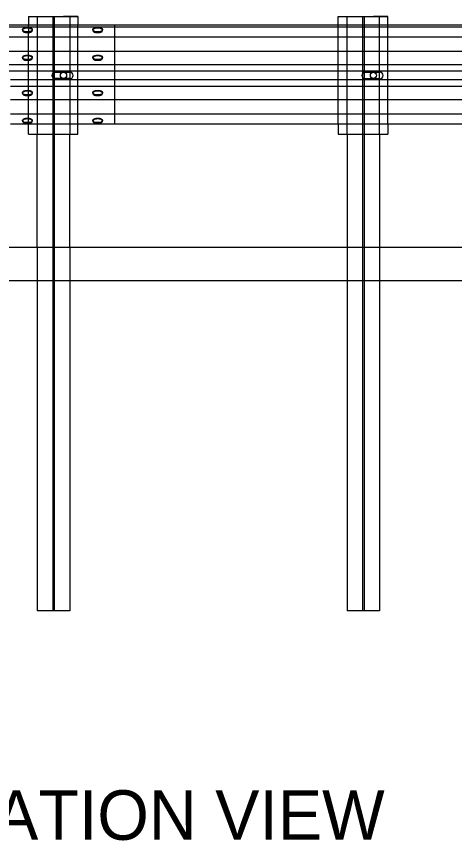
# Model space of a CAD drawing. Extents: x 49991 to 50160, y 49948 to 50051.
# Drawn here: x 50063.48 to 50067.89, y 50002.88 to 50011.2 of the extents above; entities that cross this region are included whole.
import ezdxf

# ---------------------------------------------------------------- set-up
doc = ezdxf.new("R2010")
doc.units = 0
for name, color, linetype in [('Level 1', 7, 'Continuous'), ('Level 3', 7, 'Continuous'), ('Level 4', 7, 'Continuous')]:
    doc.layers.add(name, color=color, linetype=linetype)

msp = doc.modelspace()

# ---------------------------------------------------------------- linework, layer by layer
at = {"layer": 'Level 1'}
for p, q in [((50063.598, 50011.2015), (50064.098, 50011.2015)), ((50063.598, 50011.2015), (50063.598, 50011.1187)), ((50063.6863, 50011.2015), (50064.0146, 50011.2015)), ((50064.098, 50011.2015), (50063.9521, 50011.2015)), ((50064.098, 50011.2015), (50064.098, 50011.1187)), ((50066.723, 50011.2014), (50067.223, 50011.2014)), ((50066.723, 50011.1185), (50066.723, 50011.2014)), ((50066.8113, 50011.2014), (50067.1396, 50011.2014)), ((50067.223, 50011.2014), (50067.0771, 50011.2014)), ((50067.223, 50011.1185), (50067.223, 50011.2014)), ((50057.4018, 50011.1191), (50093.8271, 50011.1169)), ((50057.4018, 50011.0986), (50093.8271, 50011.0968)), ((50063.5389, 50011.0689), (50063.5389, 50011.0616)), ((50063.5783, 50011.0909), (50063.598, 50011.0909)), ((50063.5783, 50011.0837), (50063.5783, 50011.0909)), ((50063.598, 50011.0837), (50063.5783, 50011.0837)), ((50063.598, 50011.0837), (50063.598, 50011.0909)), ((50063.598, 50011.0837), (50063.598, 50011.0469)), ((50063.6374, 50011.0616), (50063.6374, 50011.0689)), ((50064.287, 50011.0837), (50064.287, 50011.0909)), ((50064.287, 50011.0909), (50064.3066, 50011.0909)), ((50064.3066, 50011.0837), (50064.287, 50011.0837)), ((50064.3066, 50011.0837), (50064.3066, 50011.0909)), ((50064.346, 50011.0616), (50064.346, 50011.0689)), ((50058.2173, 50010.9976), (50093.8271, 50010.9976)), ((50063.598, 50011.0469), (50063.5783, 50011.0469)), ((50063.5783, 50011.0396), (50063.5783, 50011.0469)), ((50063.5783, 50011.0396), (50063.598, 50011.0396)), ((50063.598, 50011.0396), (50063.598, 50011.0469)), ((50064.3066, 50011.0469), (50064.287, 50011.0469)), ((50064.287, 50011.0396), (50064.287, 50011.0469)), ((50064.287, 50011.0396), (50064.3066, 50011.0396)), ((50064.3066, 50011.0396), (50064.3066, 50011.0469)), ((50058.2173, 50010.8525), (50093.8271, 50010.8493)), ((50063.5389, 50010.7885), (50063.5389, 50010.7812)), ((50063.5783, 50010.8105), (50063.598, 50010.8105)), ((50063.5783, 50010.8105), (50063.5783, 50010.8033)), ((50063.598, 50010.8033), (50063.5783, 50010.8033)), ((50063.5783, 50010.7665), (50063.5783, 50010.7592)), ((50063.598, 50010.7665), (50063.5783, 50010.7665)), ((50063.5783, 50010.7592), (50063.598, 50010.7592)), ((50063.598, 50010.8105), (50063.598, 50010.8033)), ((50063.598, 50010.7665), (50063.598, 50010.8033)), ((50063.598, 50010.7665), (50063.598, 50010.7592)), ((50063.6374, 50010.7812), (50063.6374, 50010.7885)), ((50064.287, 50010.8105), (50064.3066, 50010.8105)), ((50064.287, 50010.8105), (50064.287, 50010.8033)), ((50064.3066, 50010.8033), (50064.287, 50010.8033)), ((50064.287, 50010.7665), (50064.287, 50010.7592)), ((50064.3066, 50010.7665), (50064.287, 50010.7665)), ((50064.287, 50010.7592), (50064.3066, 50010.7592)), ((50064.3066, 50010.8105), (50064.3066, 50010.8033)), ((50064.3066, 50010.7665), (50064.3066, 50010.7592)), ((50064.346, 50010.7812), (50064.346, 50010.7885)), ((50058.2173, 50010.717), (50093.8271, 50010.722)), ((50060.8961, 50010.6545), (50093.8271, 50010.6434)), ((50063.8687, 50010.6396), (50064.0163, 50010.6396)), ((50064.0163, 50010.574), (50063.8687, 50010.574)), ((50066.9935, 50010.6392), (50067.1412, 50010.6392)), ((50067.1412, 50010.5736), (50066.9935, 50010.5736)), ((50093.8271, 50010.5604), (50063.4175, 50010.5609)), ((50093.8271, 50010.4957), (50063.4175, 50010.4957)), ((50063.5389, 50010.4324), (50063.5389, 50010.4252)), ((50063.5783, 50010.4545), (50063.598, 50010.4545)), ((50063.5783, 50010.4472), (50063.5783, 50010.4545)), ((50063.598, 50010.4472), (50063.5783, 50010.4472)), ((50063.598, 50010.4104), (50063.5783, 50010.4104)), ((50063.5783, 50010.4031), (50063.5783, 50010.4104)), ((50063.5783, 50010.4031), (50063.598, 50010.4031)), ((50063.598, 50010.4472), (50063.598, 50010.4545)), ((50063.598, 50010.4104), (50063.598, 50010.4472)), ((50063.598, 50010.4031), (50063.598, 50010.4104)), ((50063.6374, 50010.4252), (50063.6374, 50010.4324)), ((50064.287, 50010.4545), (50064.3066, 50010.4545)), ((50064.287, 50010.4472), (50064.287, 50010.4545)), ((50064.3066, 50010.4472), (50064.287, 50010.4472)), ((50064.3066, 50010.4104), (50064.287, 50010.4104)), ((50064.287, 50010.4031), (50064.287, 50010.4104)), ((50064.287, 50010.4031), (50064.3066, 50010.4031)), ((50064.3066, 50010.4472), (50064.3066, 50010.4545)), ((50064.3066, 50010.4031), (50064.3066, 50010.4104)), ((50064.346, 50010.4252), (50064.346, 50010.4324)), ((50093.8271, 50010.3615), (50063.4175, 50010.3611)), ((50093.8271, 50010.2161), (50063.4175, 50010.2161)), ((50063.5783, 50010.1741), (50063.598, 50010.1741)), ((50063.5783, 50010.1741), (50063.5783, 50010.1668)), ((50063.598, 50010.1668), (50063.5783, 50010.1668)), ((50063.598, 50010.1741), (50063.598, 50010.1668)), ((50063.598, 50010.13), (50063.598, 50010.1668)), ((50064.287, 50010.1741), (50064.3066, 50010.1741)), ((50064.287, 50010.1741), (50064.287, 50010.1668)), ((50064.3066, 50010.1668), (50064.287, 50010.1668)), ((50064.3066, 50010.1741), (50064.3066, 50010.1668)), ((50093.8271, 50010.1154), (50063.4175, 50010.1154)), ((50063.5389, 50010.152), (50063.5389, 50010.1448)), ((50063.5783, 50010.13), (50063.5783, 50010.1227)), ((50063.598, 50010.13), (50063.5783, 50010.13)), ((50063.5783, 50010.1227), (50063.598, 50010.1227)), ((50063.598, 50010.13), (50063.598, 50010.1227)), ((50063.598, 50010.014), (50063.598, 50010.1154)), ((50063.6374, 50010.1448), (50063.6374, 50010.152)), ((50064.098, 50010.014), (50064.098, 50010.1154)), ((50064.287, 50010.13), (50064.287, 50010.1227)), ((50064.3066, 50010.13), (50064.287, 50010.13)), ((50064.287, 50010.1227), (50064.3066, 50010.1227)), ((50064.3066, 50010.13), (50064.3066, 50010.1227)), ((50064.346, 50010.1448), (50064.346, 50010.152)), ((50066.723, 50010.1154), (50066.723, 50010.0139)), ((50067.223, 50010.1154), (50067.223, 50010.0139)), ((50063.598, 50010.014), (50064.098, 50010.014)), ((50063.6863, 50008.8682), (50063.6863, 50010.014)), ((50064.0146, 50008.8682), (50064.0146, 50010.014)), ((50066.723, 50010.0139), (50067.223, 50010.0139)), ((50066.8113, 50010.0139), (50066.8113, 50008.868)), ((50067.1396, 50010.0139), (50067.1396, 50008.868)), ((50093.8271, 50008.8669), (50039.5562, 50008.8692)), ((50034.588, 50008.5361), (50093.8271, 50008.5336))]:
    msp.add_line(p, q, dxfattribs=at)
for points in [[(50063.5783, 50011.0469), (50063.5715, 50011.0472), (50063.5648, 50011.0482), (50063.5586, 50011.0498), (50063.553, 50011.052), (50063.5481, 50011.0547), (50063.5442, 50011.0579), (50063.5413, 50011.0614), (50063.5395, 50011.0651), (50063.5389, 50011.0689), (50063.5395, 50011.0727), (50063.5413, 50011.0764), (50063.5442, 50011.0799), (50063.5481, 50011.0831), (50063.553, 50011.0858), (50063.5586, 50011.088), (50063.5648, 50011.0896), (50063.5715, 50011.0906), (50063.5783, 50011.0909)], [(50063.5783, 50011.0837), (50063.5715, 50011.0833), (50063.5648, 50011.0824), (50063.5586, 50011.0807), (50063.553, 50011.0785), (50063.5481, 50011.0758), (50063.5442, 50011.0727), (50063.5413, 50011.0692), (50063.5395, 50011.0655), (50063.5395, 50011.0653)], [(50063.598, 50011.0909), (50063.6048, 50011.0906), (50063.6115, 50011.0896), (50063.6177, 50011.088), (50063.6233, 50011.0858), (50063.6281, 50011.0831), (50063.6321, 50011.0799), (50063.635, 50011.0764), (50063.6368, 50011.0727), (50063.6374, 50011.0689), (50063.6368, 50011.0651), (50063.635, 50011.0614), (50063.6321, 50011.0579), (50063.6281, 50011.0547), (50063.6233, 50011.052), (50063.6177, 50011.0498), (50063.6115, 50011.0482), (50063.6048, 50011.0472), (50063.598, 50011.0469)], [(50063.6368, 50011.0653), (50063.6368, 50011.0655), (50063.635, 50011.0692), (50063.6321, 50011.0727), (50063.6281, 50011.0758), (50063.6233, 50011.0785), (50063.6177, 50011.0807), (50063.6115, 50011.0824), (50063.6048, 50011.0833), (50063.598, 50011.0837)], [(50064.287, 50011.0469), (50064.2801, 50011.0472), (50064.2735, 50011.0482), (50064.2673, 50011.0498), (50064.2617, 50011.052), (50064.2568, 50011.0547), (50064.2529, 50011.0579), (50064.25, 50011.0614), (50064.2482, 50011.0651), (50064.2476, 50011.0689), (50064.2482, 50011.0727), (50064.25, 50011.0764), (50064.2529, 50011.0799), (50064.2568, 50011.0831), (50064.2617, 50011.0858), (50064.2673, 50011.088), (50064.2735, 50011.0896), (50064.2801, 50011.0906), (50064.287, 50011.0909)], [(50064.287, 50011.0837), (50064.2801, 50011.0833), (50064.2735, 50011.0824), (50064.2673, 50011.0807), (50064.2617, 50011.0785), (50064.2568, 50011.0758), (50064.2529, 50011.0727), (50064.25, 50011.0692), (50064.2482, 50011.0655), (50064.2481, 50011.0653)], [(50064.3066, 50011.0909), (50064.3135, 50011.0906), (50064.3201, 50011.0896), (50064.3263, 50011.088), (50064.332, 50011.0858), (50064.3368, 50011.0831), (50064.3407, 50011.0799), (50064.3436, 50011.0764), (50064.3454, 50011.0727), (50064.346, 50011.0689), (50064.3454, 50011.0651), (50064.3436, 50011.0614), (50064.3407, 50011.0579), (50064.3368, 50011.0547), (50064.332, 50011.052), (50064.3263, 50011.0498), (50064.3201, 50011.0482), (50064.3135, 50011.0472), (50064.3066, 50011.0469)], [(50064.3455, 50011.0653), (50064.3454, 50011.0655), (50064.3436, 50011.0692), (50064.3407, 50011.0727), (50064.3368, 50011.0758), (50064.332, 50011.0785), (50064.3263, 50011.0807), (50064.3201, 50011.0824), (50064.3135, 50011.0833), (50064.3066, 50011.0837)], [(50063.5395, 50011.0653), (50063.5389, 50011.0616), (50063.5395, 50011.0578), (50063.5413, 50011.0541), (50063.5442, 50011.0506), (50063.5481, 50011.0475), (50063.553, 50011.0448), (50063.5586, 50011.0425), (50063.5648, 50011.0409), (50063.5715, 50011.0399), (50063.5783, 50011.0396)], [(50063.598, 50011.0396), (50063.6048, 50011.0399), (50063.6115, 50011.0409), (50063.6177, 50011.0425), (50063.6233, 50011.0448), (50063.6281, 50011.0475), (50063.6321, 50011.0506), (50063.635, 50011.0541), (50063.6368, 50011.0578), (50063.6374, 50011.0616), (50063.6368, 50011.0653)], [(50064.2481, 50011.0653), (50064.2476, 50011.0616), (50064.2482, 50011.0578), (50064.25, 50011.0541), (50064.2529, 50011.0506), (50064.2568, 50011.0475), (50064.2617, 50011.0448), (50064.2673, 50011.0425), (50064.2735, 50011.0409), (50064.2801, 50011.0399), (50064.287, 50011.0396)], [(50064.3066, 50011.0396), (50064.3135, 50011.0399), (50064.3201, 50011.0409), (50064.3263, 50011.0425), (50064.332, 50011.0448), (50064.3368, 50011.0475), (50064.3407, 50011.0506), (50064.3436, 50011.0541), (50064.3454, 50011.0578), (50064.346, 50011.0616), (50064.3455, 50011.0653)], [(50063.5395, 50010.7849), (50063.5389, 50010.7885), (50063.5395, 50010.7923), (50063.5413, 50010.796), (50063.5442, 50010.7995), (50063.5481, 50010.8027), (50063.553, 50010.8054), (50063.5586, 50010.8076), (50063.5648, 50010.8092), (50063.5715, 50010.8102), (50063.5783, 50010.8105)], [(50063.5783, 50010.8033), (50063.5715, 50010.8029), (50063.5648, 50010.802), (50063.5586, 50010.8003), (50063.553, 50010.7981), (50063.5481, 50010.7954), (50063.5442, 50010.7923), (50063.5413, 50010.7888), (50063.5395, 50010.7851), (50063.5389, 50010.7812), (50063.5395, 50010.7774), (50063.5413, 50010.7737), (50063.5442, 50010.7702), (50063.5481, 50010.7671), (50063.553, 50010.7644), (50063.5586, 50010.7621), (50063.5648, 50010.7605), (50063.5715, 50010.7595), (50063.5783, 50010.7592)], [(50063.5783, 50010.7665), (50063.5715, 50010.7668), (50063.5648, 50010.7678), (50063.5586, 50010.7694), (50063.553, 50010.7716), (50063.5481, 50010.7743), (50063.5442, 50010.7775), (50063.5413, 50010.781), (50063.5395, 50010.7847), (50063.5395, 50010.7849)], [(50063.598, 50010.8105), (50063.6048, 50010.8102), (50063.6115, 50010.8092), (50063.6177, 50010.8076), (50063.6233, 50010.8054), (50063.6281, 50010.8027), (50063.6321, 50010.7995), (50063.635, 50010.796), (50063.6368, 50010.7923), (50063.6374, 50010.7885), (50063.6368, 50010.7849)], [(50063.598, 50010.7592), (50063.6048, 50010.7595), (50063.6115, 50010.7605), (50063.6177, 50010.7621), (50063.6233, 50010.7644), (50063.6281, 50010.7671), (50063.6321, 50010.7702), (50063.635, 50010.7737), (50063.6368, 50010.7774), (50063.6374, 50010.7812), (50063.6368, 50010.7851), (50063.635, 50010.7888), (50063.6321, 50010.7923), (50063.6281, 50010.7954), (50063.6233, 50010.7981), (50063.6177, 50010.8003), (50063.6115, 50010.802), (50063.6048, 50010.8029), (50063.598, 50010.8033)], [(50063.6368, 50010.7849), (50063.6368, 50010.7847), (50063.635, 50010.781), (50063.6321, 50010.7775), (50063.6281, 50010.7743), (50063.6233, 50010.7716), (50063.6177, 50010.7694), (50063.6115, 50010.7678), (50063.6048, 50010.7668), (50063.598, 50010.7665)], [(50064.2481, 50010.7849), (50064.2476, 50010.7885), (50064.2482, 50010.7923), (50064.25, 50010.796), (50064.2529, 50010.7995), (50064.2568, 50010.8027), (50064.2617, 50010.8054), (50064.2673, 50010.8076), (50064.2735, 50010.8092), (50064.2801, 50010.8102), (50064.287, 50010.8105)], [(50064.287, 50010.8033), (50064.2801, 50010.8029), (50064.2735, 50010.802), (50064.2673, 50010.8003), (50064.2617, 50010.7981), (50064.2568, 50010.7954), (50064.2529, 50010.7923), (50064.25, 50010.7888), (50064.2482, 50010.7851), (50064.2476, 50010.7812), (50064.2482, 50010.7774), (50064.25, 50010.7737), (50064.2529, 50010.7702), (50064.2568, 50010.7671), (50064.2617, 50010.7644), (50064.2673, 50010.7621), (50064.2735, 50010.7605), (50064.2801, 50010.7595), (50064.287, 50010.7592)], [(50064.287, 50010.7665), (50064.2801, 50010.7668), (50064.2735, 50010.7678), (50064.2673, 50010.7694), (50064.2617, 50010.7716), (50064.2568, 50010.7743), (50064.2529, 50010.7775), (50064.25, 50010.781), (50064.2482, 50010.7847), (50064.2481, 50010.7849)], [(50064.3066, 50010.8105), (50064.3135, 50010.8102), (50064.3201, 50010.8092), (50064.3263, 50010.8076), (50064.332, 50010.8054), (50064.3368, 50010.8027), (50064.3407, 50010.7995), (50064.3436, 50010.796), (50064.3454, 50010.7923), (50064.346, 50010.7885), (50064.3455, 50010.7849)], [(50064.3066, 50010.7592), (50064.3135, 50010.7595), (50064.3201, 50010.7605), (50064.3263, 50010.7621), (50064.332, 50010.7644), (50064.3368, 50010.7671), (50064.3407, 50010.7702), (50064.3436, 50010.7737), (50064.3454, 50010.7774), (50064.346, 50010.7812), (50064.3454, 50010.7851), (50064.3436, 50010.7888), (50064.3407, 50010.7923), (50064.3368, 50010.7954), (50064.332, 50010.7981), (50064.3263, 50010.8003), (50064.3201, 50010.802), (50064.3135, 50010.8029), (50064.3066, 50010.8033)], [(50064.3455, 50010.7849), (50064.3454, 50010.7847), (50064.3436, 50010.781), (50064.3407, 50010.7775), (50064.3368, 50010.7743), (50064.332, 50010.7716), (50064.3263, 50010.7694), (50064.3201, 50010.7678), (50064.3135, 50010.7668), (50064.3066, 50010.7665)], [(50063.5783, 50010.4104), (50063.5715, 50010.4107), (50063.5648, 50010.4117), (50063.5586, 50010.4133), (50063.553, 50010.4155), (50063.5481, 50010.4182), (50063.5442, 50010.4214), (50063.5413, 50010.4249), (50063.5395, 50010.4286), (50063.5389, 50010.4324), (50063.5395, 50010.4362), (50063.5413, 50010.44), (50063.5442, 50010.4434), (50063.5481, 50010.4466), (50063.553, 50010.4493), (50063.5586, 50010.4515), (50063.5648, 50010.4531), (50063.5715, 50010.4541), (50063.5783, 50010.4545)], [(50063.5395, 50010.4288), (50063.5389, 50010.4252), (50063.5395, 50010.4213), (50063.5413, 50010.4176), (50063.5442, 50010.4141), (50063.5481, 50010.411), (50063.553, 50010.4083), (50063.5586, 50010.4061), (50063.5648, 50010.4044), (50063.5715, 50010.4034), (50063.5783, 50010.4031)], [(50063.5783, 50010.4472), (50063.5715, 50010.4469), (50063.5648, 50010.4459), (50063.5586, 50010.4442), (50063.553, 50010.442), (50063.5481, 50010.4393), (50063.5442, 50010.4362), (50063.5413, 50010.4327), (50063.5395, 50010.429), (50063.5395, 50010.4288)], [(50063.598, 50010.4545), (50063.6048, 50010.4541), (50063.6115, 50010.4531), (50063.6177, 50010.4515), (50063.6233, 50010.4493), (50063.6281, 50010.4466), (50063.6321, 50010.4434), (50063.635, 50010.44), (50063.6368, 50010.4362), (50063.6374, 50010.4324), (50063.6368, 50010.4286), (50063.635, 50010.4249), (50063.6321, 50010.4214), (50063.6281, 50010.4182), (50063.6233, 50010.4155), (50063.6177, 50010.4133), (50063.6115, 50010.4117), (50063.6048, 50010.4107), (50063.598, 50010.4104)], [(50063.6368, 50010.4288), (50063.6368, 50010.429), (50063.635, 50010.4327), (50063.6321, 50010.4362), (50063.6281, 50010.4393), (50063.6233, 50010.442), (50063.6177, 50010.4442), (50063.6115, 50010.4459), (50063.6048, 50010.4469), (50063.598, 50010.4472)], [(50063.598, 50010.4031), (50063.6048, 50010.4034), (50063.6115, 50010.4044), (50063.6177, 50010.4061), (50063.6233, 50010.4083), (50063.6281, 50010.411), (50063.6321, 50010.4141), (50063.635, 50010.4176), (50063.6368, 50010.4213), (50063.6374, 50010.4252), (50063.6368, 50010.4288)], [(50064.287, 50010.4104), (50064.2801, 50010.4107), (50064.2735, 50010.4117), (50064.2673, 50010.4133), (50064.2617, 50010.4155), (50064.2568, 50010.4182), (50064.2529, 50010.4214), (50064.25, 50010.4249), (50064.2482, 50010.4286), (50064.2476, 50010.4324), (50064.2482, 50010.4362), (50064.25, 50010.44), (50064.2529, 50010.4434), (50064.2568, 50010.4466), (50064.2617, 50010.4493), (50064.2673, 50010.4515), (50064.2735, 50010.4531), (50064.2801, 50010.4541), (50064.287, 50010.4545)], [(50064.2481, 50010.4288), (50064.2476, 50010.4252), (50064.2482, 50010.4213), (50064.25, 50010.4176), (50064.2529, 50010.4141), (50064.2568, 50010.411), (50064.2617, 50010.4083), (50064.2673, 50010.4061), (50064.2735, 50010.4044), (50064.2801, 50010.4034), (50064.287, 50010.4031)], [(50064.287, 50010.4472), (50064.2801, 50010.4469), (50064.2735, 50010.4459), (50064.2673, 50010.4442), (50064.2617, 50010.442), (50064.2568, 50010.4393), (50064.2529, 50010.4362), (50064.25, 50010.4327), (50064.2482, 50010.429), (50064.2481, 50010.4288)], [(50064.3066, 50010.4545), (50064.3135, 50010.4541), (50064.3201, 50010.4531), (50064.3263, 50010.4515), (50064.332, 50010.4493), (50064.3368, 50010.4466), (50064.3407, 50010.4434), (50064.3436, 50010.44), (50064.3454, 50010.4362), (50064.346, 50010.4324), (50064.3454, 50010.4286), (50064.3436, 50010.4249), (50064.3407, 50010.4214), (50064.3368, 50010.4182), (50064.332, 50010.4155), (50064.3263, 50010.4133), (50064.3201, 50010.4117), (50064.3135, 50010.4107), (50064.3066, 50010.4104)], [(50064.3455, 50010.4288), (50064.3454, 50010.429), (50064.3436, 50010.4327), (50064.3407, 50010.4362), (50064.3368, 50010.4393), (50064.332, 50010.442), (50064.3263, 50010.4442), (50064.3201, 50010.4459), (50064.3135, 50010.4469), (50064.3066, 50010.4472)], [(50064.3066, 50010.4031), (50064.3135, 50010.4034), (50064.3201, 50010.4044), (50064.3263, 50010.4061), (50064.332, 50010.4083), (50064.3368, 50010.411), (50064.3407, 50010.4141), (50064.3436, 50010.4176), (50064.3454, 50010.4213), (50064.346, 50010.4252), (50064.3455, 50010.4288)], [(50063.5395, 50010.1484), (50063.5389, 50010.152), (50063.5395, 50010.1558), (50063.5413, 50010.1596), (50063.5442, 50010.163), (50063.5481, 50010.1662), (50063.553, 50010.1689), (50063.5586, 50010.1711), (50063.5648, 50010.1727), (50063.5715, 50010.1737), (50063.5783, 50010.1741)], [(50063.5783, 50010.1668), (50063.5715, 50010.1665), (50063.5648, 50010.1655), (50063.5586, 50010.1638), (50063.553, 50010.1616), (50063.5481, 50010.1589), (50063.5442, 50010.1558), (50063.5413, 50010.1523), (50063.5395, 50010.1486), (50063.5389, 50010.1448), (50063.5395, 50010.1409), (50063.5413, 50010.1372), (50063.5442, 50010.1337), (50063.5481, 50010.1306), (50063.553, 50010.1279), (50063.5586, 50010.1257), (50063.5648, 50010.124), (50063.5715, 50010.123), (50063.5783, 50010.1227)], [(50063.598, 50010.1741), (50063.6048, 50010.1737), (50063.6115, 50010.1727), (50063.6177, 50010.1711), (50063.6233, 50010.1689), (50063.6281, 50010.1662), (50063.6321, 50010.163), (50063.635, 50010.1596), (50063.6368, 50010.1558), (50063.6374, 50010.152), (50063.6368, 50010.1484)], [(50063.598, 50010.1227), (50063.6048, 50010.123), (50063.6115, 50010.124), (50063.6177, 50010.1257), (50063.6233, 50010.1279), (50063.6281, 50010.1306), (50063.6321, 50010.1337), (50063.635, 50010.1372), (50063.6368, 50010.1409), (50063.6374, 50010.1448), (50063.6368, 50010.1486), (50063.635, 50010.1523), (50063.6321, 50010.1558), (50063.6281, 50010.1589), (50063.6233, 50010.1616), (50063.6177, 50010.1638), (50063.6115, 50010.1655), (50063.6048, 50010.1665), (50063.598, 50010.1668)], [(50064.2481, 50010.1484), (50064.2476, 50010.152), (50064.2482, 50010.1558), (50064.25, 50010.1596), (50064.2529, 50010.163), (50064.2568, 50010.1662), (50064.2617, 50010.1689), (50064.2673, 50010.1711), (50064.2735, 50010.1727), (50064.2801, 50010.1737), (50064.287, 50010.1741)], [(50064.287, 50010.1668), (50064.2801, 50010.1665), (50064.2735, 50010.1655), (50064.2673, 50010.1638), (50064.2617, 50010.1616), (50064.2568, 50010.1589), (50064.2529, 50010.1558), (50064.25, 50010.1523), (50064.2482, 50010.1486), (50064.2476, 50010.1448), (50064.2482, 50010.1409), (50064.25, 50010.1372), (50064.2529, 50010.1337), (50064.2568, 50010.1306), (50064.2617, 50010.1279), (50064.2673, 50010.1257), (50064.2735, 50010.124), (50064.2801, 50010.123), (50064.287, 50010.1227)], [(50064.3066, 50010.1741), (50064.3135, 50010.1737), (50064.3201, 50010.1727), (50064.3263, 50010.1711), (50064.332, 50010.1689), (50064.3368, 50010.1662), (50064.3407, 50010.163), (50064.3436, 50010.1596), (50064.3454, 50010.1558), (50064.346, 50010.152), (50064.3455, 50010.1484)], [(50064.3066, 50010.1227), (50064.3135, 50010.123), (50064.3201, 50010.124), (50064.3263, 50010.1257), (50064.332, 50010.1279), (50064.3368, 50010.1306), (50064.3407, 50010.1337), (50064.3436, 50010.1372), (50064.3454, 50010.1409), (50064.346, 50010.1448), (50064.3454, 50010.1486), (50064.3436, 50010.1523), (50064.3407, 50010.1558), (50064.3368, 50010.1589), (50064.332, 50010.1616), (50064.3263, 50010.1638), (50064.3201, 50010.1655), (50064.3135, 50010.1665), (50064.3066, 50010.1668)], [(50063.5783, 50010.13), (50063.5715, 50010.1303), (50063.5648, 50010.1313), (50063.5586, 50010.1329), (50063.553, 50010.1351), (50063.5481, 50010.1378), (50063.5442, 50010.141), (50063.5413, 50010.1445), (50063.5395, 50010.1482), (50063.5395, 50010.1484)], [(50063.6368, 50010.1484), (50063.6368, 50010.1482), (50063.635, 50010.1445), (50063.6321, 50010.141), (50063.6281, 50010.1378), (50063.6233, 50010.1351), (50063.6177, 50010.1329), (50063.6115, 50010.1313), (50063.6048, 50010.1303), (50063.598, 50010.13)], [(50064.287, 50010.13), (50064.2801, 50010.1303), (50064.2735, 50010.1313), (50064.2673, 50010.1329), (50064.2617, 50010.1351), (50064.2568, 50010.1378), (50064.2529, 50010.141), (50064.25, 50010.1445), (50064.2482, 50010.1482), (50064.2481, 50010.1484)], [(50064.3455, 50010.1484), (50064.3454, 50010.1482), (50064.3436, 50010.1445), (50064.3407, 50010.141), (50064.3368, 50010.1378), (50064.332, 50010.1351), (50064.3263, 50010.1329), (50064.3201, 50010.1313), (50064.3135, 50010.1303), (50064.3066, 50010.13)]]:
    msp.add_lwpolyline(points, dxfattribs=at)
for centre in [(50063.9521, 50010.6078), (50067.0771, 50010.6077)]:
    msp.add_circle(centre, 0.0312, dxfattribs=at)
for centre, start, end in [((50063.8687, 50010.6068), 90, 270), ((50064.0163, 50010.6068), 270, 90), ((50066.9935, 50010.6064), 90, 270), ((50067.1412, 50010.6064), 270, 90)]:
    msp.add_arc(centre, 0.0328, start, end, dxfattribs=at)
at = {"layer": 'Level 4'}
for p, q in [((50063.6863, 50011.2015), (50063.6863, 50010.014)), ((50063.8434, 50011.2015), (50063.8434, 50005.2015)), ((50063.8575, 50011.2015), (50063.8575, 50005.2015)), ((50064.0146, 50011.2015), (50064.0146, 50010.014)), ((50066.8113, 50010.0139), (50066.8113, 50011.2014)), ((50066.9684, 50011.2014), (50066.9684, 50005.2014)), ((50066.9825, 50011.2014), (50066.9825, 50005.2014)), ((50067.1396, 50010.0139), (50067.1396, 50011.2014)), ((50063.598, 50011.0909), (50063.598, 50011.1187)), ((50064.098, 50010.1154), (50064.098, 50011.1187)), ((50064.4674, 50011.1186), (50064.4674, 50011.104)), ((50064.4674, 50011.104), (50064.4674, 50011.0982)), ((50064.4674, 50011.0982), (50064.4674, 50010.9976)), ((50066.723, 50010.1154), (50066.723, 50011.1185)), ((50067.223, 50010.1154), (50067.223, 50011.1185)), ((50063.598, 50010.8105), (50063.598, 50011.0396)), ((50064.4674, 50010.9976), (50064.4674, 50010.8526)), ((50064.4674, 50010.8526), (50064.4674, 50010.718)), ((50063.598, 50010.4545), (50063.598, 50010.7592)), ((50064.4674, 50010.718), (50064.4674, 50010.6528)), ((50064.4674, 50010.6528), (50064.4674, 50010.5609)), ((50064.4674, 50010.5609), (50064.4674, 50010.4957)), ((50064.4674, 50010.4957), (50064.4674, 50010.3611)), ((50063.598, 50010.1741), (50063.598, 50010.4031)), ((50064.4674, 50010.3611), (50064.4674, 50010.2161)), ((50064.4674, 50010.2161), (50064.4674, 50010.1154)), ((50063.598, 50010.1154), (50063.598, 50010.1227)), ((50063.6863, 50008.8682), (50063.6863, 50005.2015)), ((50064.0146, 50008.8682), (50064.0146, 50005.2015)), ((50066.8113, 50008.868), (50066.8113, 50005.2014)), ((50067.1396, 50008.868), (50067.1396, 50005.2014)), ((50064.0146, 50005.2015), (50063.6863, 50005.2015)), ((50067.1396, 50005.2014), (50066.8113, 50005.2014))]:
    msp.add_line(p, q, dxfattribs=at)

# ---------------------------------------------------------------- texts
at = {"layer": 'Level 3'}
msp.add_text('ELEVATION VIEW', height=0.5, dxfattribs=at).set_placement((50061.543, 50002.8896))

doc.saveas('drawing.dxf')
